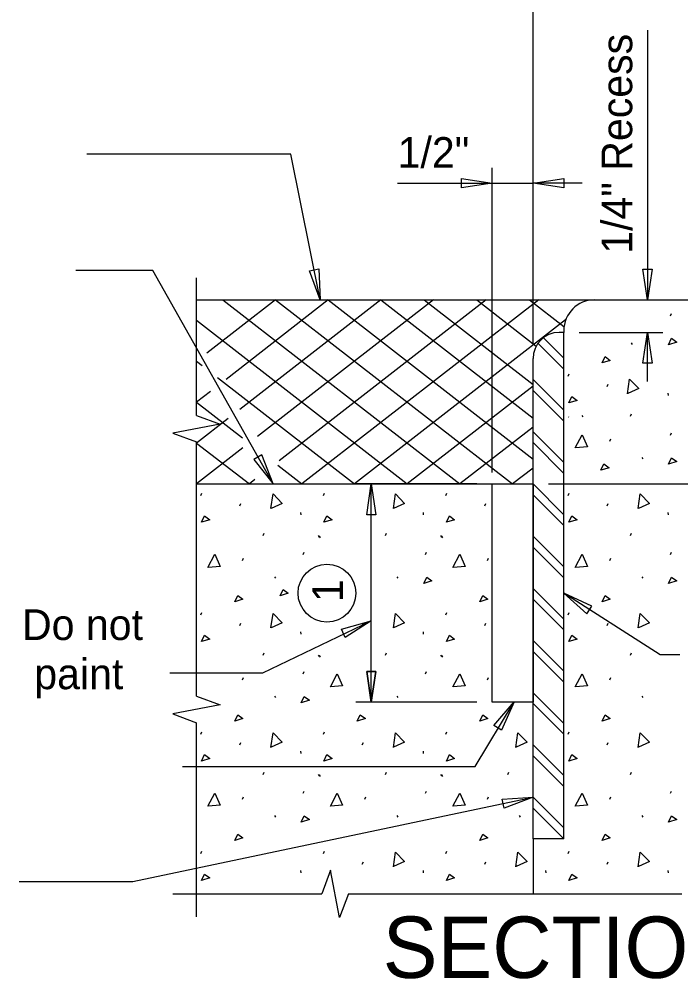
# Model space of a CAD drawing. Extents: x 2799.7 to 2896, y 515.2 to 573.9.
# Drawn here: x 2851.86 to 2859.04, y 557.93 to 568.36 of the extents above; entities that cross this region are included whole.
import ezdxf

# ---------------------------------------------------------------- set-up
doc = ezdxf.new("R2010")
doc.units = 0
for name, color, linetype in [('BR_AUTO DIMENSION', 7, 'Continuous'), ('BR_CONCRETE', 7, 'Continuous'), ('BR_DETAILS', 7, 'Continuous'), ('BR_STRUCTURAL STEEL', 7, 'Continuous'), ('BR_TABLE LINES', 7, 'Continuous'), ('BR_TEXT', 7, 'Continuous')]:
    doc.layers.add(name, color=color, linetype=linetype)

msp = doc.modelspace()

# ---------------------------------------------------------------- linework, layer by layer
at = {"layer": 'BR_AUTO DIMENSION'}
for p, q in [((2857.435, 564.972), (2857.435, 568.962)), ((2858.678, 568.237), (2858.678, 565.308)), ((2854.804, 566.891), (2852.589, 566.891)), ((2855.125, 565.308), (2854.804, 566.891)), ((2856.99, 563.474), (2856.99, 566.741)), ((2857.435, 564.835), (2857.435, 566.741)), ((2856.99, 563.431), (2856.99, 566.717)), ((2855.965, 566.574), (2856.99, 566.574)), ((2856.457, 566.574), (2856.99, 566.574)), ((2856.99, 566.574), (2857.435, 566.574)), ((2857.968, 566.574), (2857.435, 566.574)), ((2853.308, 565.627), (2852.471, 565.627)), ((2854.612, 563.308), (2853.308, 565.627)), ((2858.268, 565.308), (2858.845, 565.308)), ((2857.935, 564.953), (2858.845, 564.953)), ((2858.678, 564.42), (2858.678, 564.953)), ((2856.824, 563.308), (2855.512, 563.308)), ((2855.679, 560.937), (2855.679, 563.308)), ((2857.602, 563.308), (2863.523, 563.308)), ((2858.816, 561.453), (2857.769, 562.122)), ((2854.503, 561.255), (2855.679, 561.822)), ((2859.03, 561.453), (2858.816, 561.453)), ((2853.491, 561.255), (2854.503, 561.255)), ((2856.824, 560.937), (2855.512, 560.937)), ((2856.808, 560.24), (2857.23, 560.94)), ((2853.631, 560.24), (2856.808, 560.24)), ((2853.09, 558.991), (2857.435, 559.906)), ((2851.856, 558.991), (2853.09, 558.991))]:
    msp.add_line(p, q, dxfattribs=at)
for points in [[(2856.657, 566.624), (2856.99, 566.574), (2856.657, 566.524)], [(2857.768, 566.524), (2857.435, 566.574), (2857.768, 566.624)], [(2855.108, 565.644), (2855.125, 565.308), (2855.01, 565.624)], [(2858.728, 565.641), (2858.678, 565.308), (2858.628, 565.641)], [(2858.628, 564.62), (2858.678, 564.953), (2858.728, 564.62)], [(2854.405, 563.574), (2854.612, 563.308), (2854.492, 563.623)], [(2855.629, 562.974), (2855.679, 563.308), (2855.729, 562.974)], [(2855.629, 562.974), (2855.679, 563.308), (2855.729, 562.974)], [(2858.075, 561.979), (2857.769, 562.122), (2858.019, 561.896)], [(2855.354, 561.731), (2855.679, 561.822), (2855.395, 561.64)], [(2855.629, 561.27), (2855.679, 560.937), (2855.729, 561.27)], [(2855.729, 561.27), (2855.679, 560.937), (2855.629, 561.27)], [(2857.008, 560.686), (2857.23, 560.94), (2857.092, 560.632)], [(2857.099, 559.883), (2857.435, 559.906), (2857.12, 559.786)]]:
    msp.add_lwpolyline(points, close=True, dxfattribs=at)
msp.add_circle((2855.198, 562.122), 0.314, dxfattribs=at)
at = {"layer": 'BR_CONCRETE'}
for p, q in [((2858.102, 565.308), (2862.356, 565.308)), ((2857.768, 564.974), (2857.768, 564.953)), ((2853.783, 563.308), (2856.99, 563.308)), ((2857.435, 559.455), (2857.435, 558.858))]:
    msp.add_line(p, q, dxfattribs=at)
msp.add_arc((2858.102, 564.974), 0.333, 90, 180, dxfattribs=at)
at = {"layer": 'BR_DETAILS'}
for p, q in [((2858.926, 565.134), (2858.937, 565.159)), ((2858.501, 564.84), (2858.512, 564.823)), ((2857.818, 564.479), (2857.829, 564.504)), ((2858.24, 564.365), (2858.251, 564.39)), ((2858.9, 564.295), (2858.903, 564.27)), ((2857.819, 564.038), (2857.822, 564.034)), ((2857.964, 564.053), (2857.976, 564.037)), ((2858.493, 564.043), (2858.504, 564.068)), ((2858.926, 563.837), (2858.937, 563.862)), ((2858.268, 563.774), (2858.279, 563.799)), ((2858.615, 563.596), (2858.626, 563.579)), ((2853.83, 563.182), (2853.841, 563.207)), ((2855.16, 563.182), (2855.171, 563.207)), ((2856.489, 563.182), (2856.5, 563.207)), ((2857.818, 563.182), (2857.829, 563.207)), ((2854.252, 563.069), (2854.263, 563.094)), ((2856.911, 563.069), (2856.922, 563.094)), ((2858.24, 563.069), (2858.251, 563.094)), ((2854.912, 562.999), (2854.915, 562.974)), ((2856.241, 562.999), (2856.244, 562.974)), ((2858.9, 562.999), (2858.903, 562.974)), ((2854.505, 562.747), (2854.516, 562.772)), ((2855.101, 562.747), (2855.112, 562.73)), ((2855.112, 562.74), (2855.124, 562.724)), ((2855.834, 562.747), (2855.845, 562.772)), ((2856.431, 562.747), (2856.442, 562.73)), ((2856.442, 562.74), (2856.453, 562.724)), ((2858.493, 562.747), (2858.504, 562.772)), ((2854.28, 562.477), (2854.291, 562.502)), ((2854.938, 562.541), (2854.949, 562.566)), ((2856.267, 562.541), (2856.278, 562.566)), ((2856.939, 562.477), (2856.95, 562.502)), ((2858.268, 562.477), (2858.279, 562.502)), ((2858.926, 562.541), (2858.937, 562.566)), ((2854.627, 562.3), (2854.638, 562.283)), ((2855.956, 562.3), (2855.967, 562.283)), ((2858.615, 562.3), (2858.626, 562.283)), ((2853.83, 561.886), (2853.841, 561.911)), ((2856.489, 561.886), (2856.5, 561.911)), ((2857.818, 561.886), (2857.829, 561.911)), ((2854.252, 561.772), (2854.263, 561.797)), ((2855.581, 561.772), (2855.593, 561.797)), ((2856.911, 561.772), (2856.922, 561.797)), ((2858.24, 561.772), (2858.251, 561.797)), ((2854.912, 561.703), (2854.915, 561.678)), ((2856.241, 561.703), (2856.244, 561.678)), ((2854.505, 561.45), (2854.516, 561.475)), ((2855.101, 561.45), (2855.112, 561.434)), ((2855.112, 561.444), (2855.124, 561.427)), ((2855.834, 561.45), (2855.845, 561.475)), ((2856.431, 561.45), (2856.442, 561.434)), ((2856.442, 561.444), (2856.453, 561.427)), ((2858.493, 561.45), (2858.504, 561.475)), ((2854.938, 561.245), (2854.949, 561.27)), ((2856.267, 561.245), (2856.278, 561.27)), ((2854.28, 561.181), (2854.291, 561.206)), ((2856.939, 561.181), (2856.95, 561.206)), ((2858.268, 561.181), (2858.279, 561.206)), ((2854.627, 561.003), (2854.638, 560.987)), ((2855.956, 561.003), (2855.967, 560.987)), ((2858.615, 561.003), (2858.626, 560.987)), ((2853.83, 560.59), (2853.841, 560.615)), ((2855.16, 560.59), (2855.171, 560.615)), ((2856.489, 560.59), (2856.5, 560.615)), ((2857.818, 560.59), (2857.829, 560.615)), ((2854.252, 560.476), (2854.263, 560.501)), ((2855.581, 560.476), (2855.593, 560.501)), ((2858.24, 560.476), (2858.251, 560.501)), ((2854.912, 560.406), (2854.915, 560.381)), ((2856.241, 560.406), (2856.244, 560.381)), ((2854.505, 560.154), (2854.516, 560.179)), ((2855.834, 560.154), (2855.845, 560.179)), ((2857.163, 560.154), (2857.174, 560.179)), ((2858.493, 560.154), (2858.504, 560.179)), ((2855.101, 560.154), (2855.112, 560.137)), ((2855.112, 560.148), (2855.124, 560.131)), ((2856.431, 560.154), (2856.442, 560.137)), ((2856.442, 560.148), (2856.453, 560.131)), ((2854.938, 559.948), (2854.949, 559.973)), ((2856.267, 559.948), (2856.278, 559.973)), ((2858.926, 559.948), (2858.937, 559.973)), ((2854.28, 559.884), (2854.291, 559.909)), ((2855.609, 559.884), (2855.62, 559.909)), ((2856.939, 559.884), (2856.95, 559.909)), ((2858.268, 559.884), (2858.279, 559.909)), ((2854.627, 559.707), (2854.638, 559.69)), ((2855.956, 559.707), (2855.967, 559.69)), ((2857.285, 559.707), (2857.297, 559.69)), ((2858.615, 559.707), (2858.626, 559.69)), ((2853.83, 559.293), (2853.841, 559.318)), ((2855.16, 559.293), (2855.171, 559.318)), ((2856.489, 559.293), (2856.5, 559.318)), ((2857.818, 559.293), (2857.829, 559.318)), ((2855.581, 559.18), (2855.593, 559.205)), ((2856.911, 559.18), (2856.922, 559.205)), ((2858.24, 559.18), (2858.251, 559.205)), ((2854.912, 559.11), (2854.915, 559.085)), ((2856.241, 559.11), (2856.244, 559.085)), ((2857.571, 559.11), (2857.573, 559.085)), ((2858.9, 559.11), (2858.903, 559.085)), ((2853.525, 558.858), (2855.142, 558.858)), ((2855.431, 558.858), (2859.049, 558.858))]:
    msp.add_line(p, q, dxfattribs=at)
for points in [[(2853.783, 564.053), (2853.783, 565.546)], [(2858.906, 564.82), (2858.94, 564.89), (2858.995, 564.848), (2858.906, 564.82)], [(2858.185, 564.622), (2858.219, 564.691), (2858.274, 564.65), (2858.185, 564.622)], [(2858.461, 564.288), (2858.483, 564.447), (2858.583, 564.344), (2858.464, 564.289)], [(2857.824, 564.187), (2857.857, 564.257), (2857.913, 564.215), (2857.824, 564.187)], [(2853.783, 564.053), (2854.04, 563.957), (2853.526, 563.86), (2853.783, 563.764)], [(2857.893, 563.699), (2857.968, 563.84), (2858.027, 563.71), (2857.896, 563.699)], [(2853.783, 561.004), (2853.783, 563.764)], [(2858.171, 563.457), (2858.204, 563.526), (2858.26, 563.484), (2858.171, 563.457)], [(2858.906, 563.524), (2858.94, 563.593), (2858.995, 563.552), (2858.906, 563.524)], [(2854.59, 563.04), (2854.612, 563.199), (2854.711, 563.096), (2854.592, 563.041)], [(2855.919, 563.04), (2855.941, 563.199), (2856.04, 563.096), (2855.922, 563.041)], [(2858.578, 563.04), (2858.6, 563.199), (2858.699, 563.096), (2858.58, 563.041)], [(2853.836, 562.891), (2853.869, 562.96), (2853.925, 562.919), (2853.836, 562.891)], [(2855.165, 562.891), (2855.198, 562.96), (2855.254, 562.919), (2855.165, 562.891)], [(2856.495, 562.891), (2856.528, 562.96), (2856.583, 562.919), (2856.495, 562.891)], [(2857.824, 562.891), (2857.857, 562.96), (2857.913, 562.919), (2857.824, 562.891)], [(2853.905, 562.402), (2853.98, 562.544), (2854.038, 562.413), (2853.908, 562.402)], [(2856.564, 562.402), (2856.639, 562.544), (2856.697, 562.413), (2856.567, 562.402)], [(2857.893, 562.402), (2857.968, 562.544), (2858.027, 562.413), (2857.896, 562.402)], [(2856.248, 562.227), (2856.281, 562.297), (2856.336, 562.255), (2856.248, 562.227)], [(2858.906, 562.227), (2858.94, 562.297), (2858.995, 562.255), (2858.906, 562.227)], [(2854.688, 562.093), (2854.721, 562.163), (2854.777, 562.121), (2854.688, 562.093)], [(2854.197, 562.029), (2854.23, 562.098), (2854.286, 562.057), (2854.197, 562.029)], [(2856.856, 562.029), (2856.889, 562.098), (2856.945, 562.057), (2856.856, 562.029)], [(2858.185, 562.029), (2858.219, 562.098), (2858.274, 562.057), (2858.185, 562.029)], [(2854.59, 561.744), (2854.612, 561.902), (2854.711, 561.8), (2854.592, 561.745)], [(2855.919, 561.744), (2855.941, 561.902), (2856.04, 561.8), (2855.922, 561.745)], [(2858.578, 561.744), (2858.6, 561.902), (2858.699, 561.8), (2858.58, 561.745)], [(2853.836, 561.595), (2853.869, 561.664), (2853.925, 561.622), (2853.836, 561.595)], [(2856.495, 561.595), (2856.528, 561.664), (2856.583, 561.622), (2856.495, 561.595)], [(2857.824, 561.595), (2857.857, 561.664), (2857.913, 561.622), (2857.824, 561.595)], [(2855.235, 561.106), (2855.309, 561.247), (2855.368, 561.117), (2855.237, 561.106)], [(2856.564, 561.106), (2856.639, 561.247), (2856.697, 561.117), (2856.567, 561.106)], [(2857.893, 561.106), (2857.968, 561.247), (2858.027, 561.117), (2857.896, 561.106)], [(2853.783, 561.004), (2854.04, 560.908), (2853.526, 560.811), (2853.783, 560.715)], [(2854.918, 560.931), (2854.951, 561), (2855.007, 560.959), (2854.918, 560.931)], [(2854.197, 560.733), (2854.23, 560.802), (2854.286, 560.76), (2854.197, 560.733)], [(2855.527, 560.733), (2855.56, 560.802), (2855.615, 560.76), (2855.527, 560.733)], [(2856.856, 560.733), (2856.889, 560.802), (2856.945, 560.76), (2856.856, 560.733)], [(2858.185, 560.733), (2858.219, 560.802), (2858.274, 560.76), (2858.185, 560.733)], [(2853.783, 558.606), (2853.783, 560.715)], [(2854.59, 560.447), (2854.612, 560.606), (2854.711, 560.503), (2854.592, 560.448)], [(2855.919, 560.447), (2855.941, 560.606), (2856.04, 560.503), (2855.922, 560.448)], [(2857.248, 560.447), (2857.27, 560.606), (2857.37, 560.503), (2857.251, 560.448)], [(2858.578, 560.447), (2858.6, 560.606), (2858.699, 560.503), (2858.58, 560.448)], [(2853.836, 560.298), (2853.869, 560.368), (2853.925, 560.326), (2853.836, 560.298)], [(2855.165, 560.298), (2855.198, 560.368), (2855.254, 560.326), (2855.165, 560.298)], [(2856.495, 560.298), (2856.528, 560.368), (2856.583, 560.326), (2856.495, 560.298)], [(2857.824, 560.298), (2857.857, 560.368), (2857.913, 560.326), (2857.824, 560.298)], [(2853.905, 559.81), (2853.98, 559.951), (2854.038, 559.821), (2853.908, 559.81)], [(2855.235, 559.81), (2855.309, 559.951), (2855.368, 559.821), (2855.237, 559.81)], [(2856.564, 559.81), (2856.639, 559.951), (2856.697, 559.821), (2856.567, 559.81)], [(2857.893, 559.81), (2857.968, 559.951), (2858.027, 559.821), (2857.896, 559.81)], [(2854.918, 559.635), (2854.951, 559.704), (2855.007, 559.662), (2854.918, 559.635)], [(2858.906, 559.635), (2858.94, 559.704), (2858.995, 559.662), (2858.906, 559.635)], [(2854.197, 559.436), (2854.23, 559.506), (2854.286, 559.464), (2854.197, 559.436)], [(2856.856, 559.436), (2856.889, 559.506), (2856.945, 559.464), (2856.856, 559.436)], [(2858.185, 559.436), (2858.219, 559.506), (2858.274, 559.464), (2858.185, 559.436)], [(2855.919, 559.151), (2855.941, 559.31), (2856.04, 559.207), (2855.922, 559.152)], [(2857.248, 559.151), (2857.27, 559.31), (2857.37, 559.207), (2857.251, 559.152)], [(2858.578, 559.151), (2858.6, 559.31), (2858.699, 559.207), (2858.58, 559.152)], [(2853.836, 559.002), (2853.869, 559.071), (2853.925, 559.03), (2853.836, 559.002)], [(2855.431, 558.858), (2855.335, 558.6), (2855.238, 559.115), (2855.142, 558.858)], [(2856.495, 559.002), (2856.528, 559.071), (2856.583, 559.03), (2856.495, 559.002)], [(2857.824, 559.002), (2857.857, 559.071), (2857.913, 559.03), (2857.824, 559.002)]]:
    msp.add_lwpolyline(points, dxfattribs=at)
at = {"layer": 'BR_STRUCTURAL STEEL'}
for p, q in [((2857.547, 564.895), (2857.768, 564.674)), ((2857.768, 564.953), (2857.719, 564.953)), ((2857.768, 559.455), (2857.768, 564.953)), ((2857.489, 564.835), (2857.768, 564.556)), ((2857.435, 559.455), (2857.435, 564.669)), ((2857.435, 564.441), (2857.768, 564.108)), ((2857.435, 564.323), (2857.768, 563.99)), ((2857.435, 563.874), (2857.768, 563.541)), ((2857.435, 563.757), (2857.768, 563.423)), ((2857.435, 563.308), (2857.768, 562.974)), ((2857.435, 563.19), (2857.768, 562.856)), ((2857.435, 562.741), (2857.768, 562.407)), ((2857.435, 562.623), (2857.768, 562.289)), ((2857.435, 562.174), (2857.768, 561.84)), ((2857.435, 562.056), (2857.768, 561.723)), ((2857.435, 561.607), (2857.768, 561.274)), ((2857.435, 561.489), (2857.768, 561.156)), ((2857.435, 561.04), (2857.768, 560.707)), ((2857.435, 560.922), (2857.768, 560.589)), ((2857.435, 560.473), (2857.768, 560.14)), ((2857.435, 560.355), (2857.768, 560.022)), ((2857.435, 559.906), (2857.768, 559.573)), ((2857.435, 559.788), (2857.768, 559.455)), ((2857.768, 559.455), (2857.435, 559.455))]:
    msp.add_line(p, q, dxfattribs=at)
msp.add_arc((2857.719, 564.669), 0.284, 90, 180, dxfattribs=at)
at = {"layer": 'BR_TABLE LINES'}
for p, q in [((2853.783, 565.308), (2858.102, 565.308)), ((2854.64, 565.308), (2853.893, 564.727)), ((2854.069, 565.308), (2856.64, 563.308)), ((2855.212, 565.308), (2854.102, 564.444)), ((2855.783, 565.308), (2854.252, 564.117)), ((2856.355, 565.308), (2854.445, 563.822)), ((2854.64, 565.308), (2857.212, 563.308)), ((2856.926, 565.308), (2854.678, 563.559)), ((2857.498, 565.308), (2854.926, 563.308)), ((2855.212, 565.308), (2857.435, 563.578)), ((2855.783, 565.308), (2857.435, 564.023)), ((2856.254, 565.308), (2857.435, 564.389)), ((2856.825, 565.308), (2857.47, 564.806)), ((2857.396, 565.308), (2857.771, 565.016)), ((2853.783, 565.085), (2856.069, 563.308)), ((2857.789, 565.09), (2855.497, 563.308)), ((2853.783, 564.641), (2853.843, 564.595)), ((2854.011, 564.464), (2855.497, 563.308)), ((2857.435, 564.37), (2856.069, 563.308)), ((2853.932, 564.312), (2853.783, 564.196)), ((2853.783, 564.196), (2854.281, 563.809)), ((2854.125, 564.018), (2853.783, 563.752)), ((2857.435, 563.926), (2856.64, 563.308)), ((2853.783, 563.752), (2854.355, 563.308)), ((2854.286, 563.699), (2853.783, 563.308)), ((2854.665, 563.511), (2854.926, 563.308)), ((2857.435, 563.481), (2857.212, 563.308)), ((2854.415, 563.355), (2854.355, 563.308))]:
    msp.add_line(p, q, dxfattribs=at)
msp.add_lwpolyline([(2856.99, 563.308), (2857.435, 563.308), (2857.435, 560.937), (2856.99, 560.937)], close=True, dxfattribs=at)

# ---------------------------------------------------------------- texts
at = {"layer": 'BR_AUTO DIMENSION'}
msp.add_text('1/4" Recess', height=0.33335, rotation=90, dxfattribs=at).set_placement((2858.512, 565.808))
msp.add_text('1/2"', height=0.3334, dxfattribs=at).set_placement((2855.965, 566.741))
at = {"layer": 'BR_TEXT'}
msp.add_text('1', height=0.333, rotation=90, dxfattribs=at).set_placement((2855.372, 562.025))
for s, height, p in [('Do not', 0.3333, (2851.887, 561.613)), ('paint', 0.3333, (2852.02, 561.079)), ('SECTION C-C', 0.66673, (2855.803, 557.943))]:
    msp.add_text(s, height=height, dxfattribs=at).set_placement(p)

doc.saveas('drawing.dxf')
